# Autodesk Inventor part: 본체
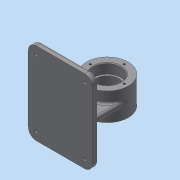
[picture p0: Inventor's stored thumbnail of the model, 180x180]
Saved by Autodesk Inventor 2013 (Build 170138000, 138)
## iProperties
Created: 2019-09
Part Number: 본체
Material: 일반
Document SubType Name: Modeling
Designer: Administrator
Density: 1 g/cm^3
Author: Administrator
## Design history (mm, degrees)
sketch "스케치1"
  geometry: C1 r 32 at (0, 0); 1 further point
  constraints: 1 centre point, 1 coincident
  dimensions: "d0" = 64 diameter of C1
extrude "돌출1" new body sketch "스케치1" stored distance "d1" = 42; taper "d2" = 0 deg
sketch "스케치2"
  geometry: C1 r 32 at (0, 0) reference
hole "구멍1" sketch "스케치2" at (0, 0) diameter "d3" = 36; stored, may be unused: countersink angle "d7" = 90 deg, drill point angle "d9" = 118 deg; dims "d4" = 6, "d5" = 42, "d6" = 15, "d8" = 8
sketch "스케치3"
  geometry: C1 r 18 at (0, 0) reference; C2 r 32 at (0, 0) reference; C3 r 21 at (0, 0)
  constraints: 1 centre point, 1 coincident
  dimensions: "d10" = 42 diameter of C3
extrude "돌출2" cut sketch "스케치3" distance "d11" = 15; taper "d12" = 0 deg
sketch "스케치4"
  geometry: C1 r 21 at (0, 0) reference; 1 further point
  constraints: 1 vertical alignment
  dimensions: "d13" = 26 distance of C1.centre point (0, 26)
hole "구멍2" sketch "스케치4" at (0, 26) diameter "d14" = 3.242; stored, may be unused: countersink angle "d18" = 90 deg, drill point angle "d20" = 118 deg; dims "d15" = 8, "d16" = 42, "d17" = 15, "d19" = 10
sketch "스케치6"
  geometry: L1 (-62, -59)-(36, -59); L2 (36, -59)-(36, -50); L3 (36, -50)-(-62, -50); L4 (-62, -50)-(-62, -59); 1 further point
  constraints: 8 end point, 2 parallel, 1 horizontal, 1 perpendicular
  dimensions: "d30" = 59 distance from line of L1 point (0, 0); "d31" = 98 distance of L1.start L1.end; "d32" = 36 horizontal distance of L1.end point (0, 0); "d33" = 9 distance of L1.end L2.end
extrude "돌출4" join sketch "스케치6" stored distance "d34" = 126; taper "d35" = 0 deg
fillet "모깎기1" dims "d36" = 12
sketch "스케치8"
  geometry: L1 (24, -50)-(-50, -50) reference; L2 (24, -50)-(24, -59) reference; L3 (24, -50)-(-50, -50) reference; L4 (-50, -59)-(-50, -50) reference; L5 (-50, -59)-(24, -59) reference; L6 (24, -50)-(36, -50) reference; L7 (-32, 0)-(-32, -50); L8 (32, 0)-(32, -50); A1 r 32 centre (0, 0) between (-32, 0) and (32, 0) reference; 1 further point
  constraints: 4 end point, 2 perpendicular, 2 point on circle, 2 point on line, 2 tangent
extrude "돌출5" join sketch "스케치8" stored distance "d37" = 8; taper "d38" = 0 deg
sketch "스케치9"
  geometry: L1 (-12, -12)-(-12, -114) reference; L2 (54, -80)-(46, -80); L3 (46, -80)-(46, -46); L4 (46, -46)-(54, -46); L5 (54, -46)-(54, -80); L6 (46, -63)-(54, -63); 2 further points
  constraints: 10 end point, 2 midpoint, 2 parallel, 1 horizontal, 1 perpendicular
  dimensions: "d39" = 34 distance of L2.end L3.end; "d41" = 8 distance of L2.start L2.end; "d42" = 58 distance from line of L3.end L1; "d43" = 63 vertical distance of point (0, 0) L6.start
extrude "돌출6" join sketch "스케치9" stored distance "d44" = 8; taper "d45" = 0 deg
sketch "스케치10"
  geometry: A1 r 12 centre (74, -12) between (86, -12) and (74, 0) reference; A2 r 12 centre (0, -12) between (0, 0) and (-12, -12) reference; A3 r 12 centre (0, -114) between (-12, -114) and (0, -126) reference; A4 r 12 centre (74, -114) between (74, -126) and (86, -114) reference; 5 further points
  constraints: 4 coincident
hole "구멍3" sketch "스케치10" at (0, -12), (0, -114), (74, -114), (74, -12) diameter "d46" = 4.5; stored, may be unused: countersink angle "d50" = 90 deg, drill point angle "d52" = 118 deg; dims "d47" = 8, "d48" = 8, "d49" = 4.4, "d51" = 10
sketch "스케치11"
  geometry: L1 (-12, -12)-(-12, -114) reference; 3 further points
  constraints: 1 other
  dimensions: "d53" = 63 vertical distance of point (0, 0) point (-2, -63); "d54" = 10 distance from line of point (-2, -63) L1
feature "엠보싱1" sketch "스케치11" dims "d55" = 0.5, "d56" = 0
fillet "모깎기2" dims "d57" = 3
fillet "모깎기3" dims "d58" = 3
chamfer "모따기1" distance "d59" = 1; stored, may be unused: second distance "d60" = 2, angle "d61" = 45 deg
fillet "모깎기4" dims "d62" = 0.3
node "솔리드1"
pattern_circular "원형 패턴1" dims angle "d22" = 360 deg
mirror "대칭1"
node "투영된 루프1"
